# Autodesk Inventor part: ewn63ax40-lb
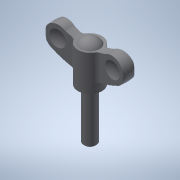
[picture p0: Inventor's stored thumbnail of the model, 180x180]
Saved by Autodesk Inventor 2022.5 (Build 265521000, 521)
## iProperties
Created: 2017-05
Part Number: ewn63ax40-lb
Material: 一般
Document SubType Name: Modeling
Designer: imaocorp
Density: 1 g/cm^3
Appearance: 既定
Author: imaocorp
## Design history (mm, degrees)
node "ewn63ax40-lb.x_t1"
node "ewn63ax40-lb"
node "Base1"
